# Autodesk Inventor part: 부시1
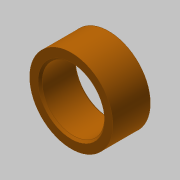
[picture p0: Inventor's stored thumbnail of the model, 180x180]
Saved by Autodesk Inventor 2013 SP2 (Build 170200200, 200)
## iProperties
Created: 2016-08
Part Number: 부시1
Material: 강철, 탄소
Document SubType Name: Modeling
Designer: mduedu
Density: 7.87 g/cm^3
Author: mduedu
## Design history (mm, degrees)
sketch "스케치1"
  geometry: C1 r 7.5 at (0, 0); C2 r 10 at (0, 0); 1 further point
  constraints: 2 centre point, 2 coincident
  dimensions: "d0" = 15 diameter of C1; "d1" = 20 diameter of C2
extrude "돌출1" new body sketch "스케치1" stored distance "d2" = 9; taper "d3" = 0 deg
chamfer "모따기1" distance "d4" = 0.5; stored, may be unused: second distance "d5" = 2, angle "d6" = 45 deg
node "솔리드1"
